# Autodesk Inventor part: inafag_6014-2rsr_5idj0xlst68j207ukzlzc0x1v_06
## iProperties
Shininess: 64.0
Angle Display Precision: 2
Document Length Units: 11269
Document Angle Units: 11279
Document Time Units: 11290
Document Mass Units: 11283
Document Length Units Precision: 3
Document Angle Units Precision: 2
Compacted: True
Created: 2008-08
Part Number: inafag_6014-2rsr_5idj0xlst68j207ukzlzc0x1v_06
Document SubType Name: Modeling
Designer: tpomodeler
Density: 0.0
Volumn: 0.0
Area: 0.0
PropertySet Name: Model Information
Control State: 0
Master: False
Checked Out: False
Author: tpomodeler
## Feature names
1. inafag_6014-2rsr_5idj0xlst68j207ukzlzc0x1v
